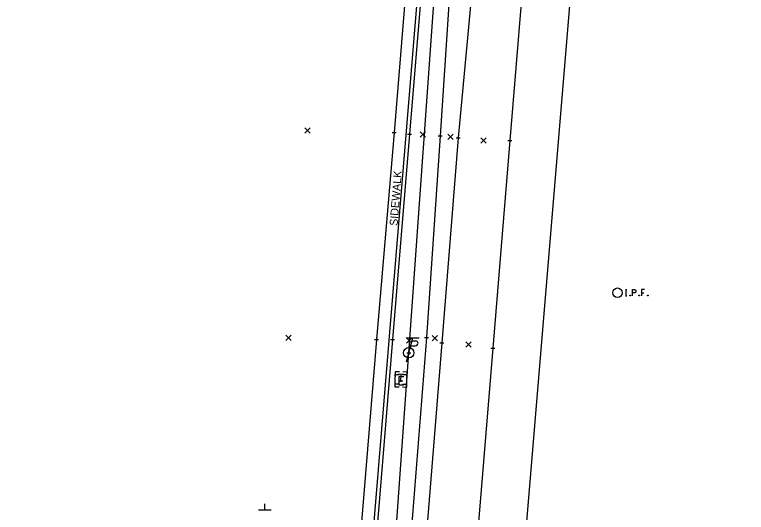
# Model space of a CAD drawing. Extents: x 1380440 to 1381945, y 468756 to 470369.
# Drawn here: x 1381482.8 to 1381665.6, y 469978.3 to 470102.7 of the extents above; entities that cross this region are included whole.
import ezdxf

# ---------------------------------------------------------------- set-up
doc = ezdxf.new("R2010")
doc.units = 0
for name, color, linetype in [('DR_P_Headwall', 7, 'Continuous'), ('GE_P_Driveway_CL', 7, 'Continuous'), ('PM_P_Cells', 7, 'Continuous'), ('PM_X_Cells', 7, 'Continuous'), ('PM_X_CL_Double_Solid', 7, 'Continuous'), ('PV_P_Curb', 7, 'Continuous'), ('PV_P_Drive', 7, 'Continuous'), ('PV_X_COP', 7, 'Continuous'), ('RW_P_Esmt_TMP', 7, 'Continuous'), ('SC_Scratch1', 7, 'Continuous'), ('SC_Shading1', 7, 'Continuous'), ('SH_Named_Boundary', 7, 'Continuous'), ('UT_X_Gas', 7, 'Continuous'), ('UT_X_Overhead_Combined', 7, 'Continuous'), ('UT_X_Water', 7, 'Continuous'), ('X-SUBDIVISION', 7, 'Continuous')]:
    doc.layers.add(name, color=color, linetype=linetype)

msp = doc.modelspace()

# ---------------------------------------------------------------- linework, layer by layer
at = {"layer": 'DR_P_Headwall'}
for points in [[(1381595.25, 470241), (1381595.01, 470239.38), (1381594.79, 470235.56), (1381591.94, 470203.13), (1381590.15, 470180.15), (1381585.84, 470126.11), (1381581.45, 470072.84), (1381577.22, 470021.47), (1381573.16, 469971.68), (1381569.7, 469929.43), (1381565.6, 469880.89), (1381564.41, 469867), (1381562.95, 469848.39), (1381561.9, 469840.88)], [(1381542.56, 470237.64), (1381568.34, 470236.69), (1381578.51, 470236.26), (1381584.49, 470236.02), (1381590.64, 470235.62), (1381587.95, 470203.42), (1381586.62, 470180.46), (1381581.93, 470126.46), (1381577.65, 470073.24), (1381573.2, 470021.54), (1381569.15, 469971.74), (1381565.64, 469929.65), (1381561.64, 469881.16), (1381560.46, 469867.32), (1381559.27, 469848.71), (1381558.35, 469840.14)]]:
    msp.add_lwpolyline(points, dxfattribs=at)
at = {"layer": 'GE_P_Driveway_CL'}
for p, q in [((1381555.34, 470073.03), (1381556.68, 470074.37)), ((1381555.34, 470074.37), (1381556.68, 470073.03)), ((1381584.13, 470072.03), (1381585.46, 470073.37)), ((1381584.13, 470073.37), (1381585.46, 470072.03)), ((1381591, 470071.5), (1381592.33, 470072.83)), ((1381591, 470072.83), (1381592.33, 470071.5)), ((1381599.22, 470070.57), (1381600.56, 470071.9)), ((1381599.22, 470071.9), (1381600.56, 470070.57)), ((1381550.55, 470021.28), (1381551.88, 470022.61)), ((1381550.55, 470022.61), (1381551.88, 470021.28)), ((1381587.09, 470021.17), (1381588.43, 470022.51)), ((1381587.09, 470022.51), (1381588.43, 470021.17)), ((1381580.68, 470020.59), (1381582.01, 470021.92)), ((1381580.68, 470021.92), (1381582.01, 470020.59)), ((1381595.47, 470019.55), (1381596.81, 470020.89)), ((1381595.47, 470020.89), (1381596.81, 470019.55))]:
    msp.add_line(p, q, dxfattribs=at)
at = {"layer": 'PM_P_Cells'}
for p, q in [((1381578.68, 470012.9), (1381579.98, 470012.87)), ((1381579.28, 470010.89), (1381579.33, 470012.89)), ((1381579.3, 470011.89), (1381579.3, 470011.89))]:
    msp.add_line(p, q, dxfattribs=at)
for points in [[(1381578.94, 470013.4), (1381577.84, 470013.42), (1381577.81, 470012.32)], [(1381580.81, 470012.26), (1381580.84, 470013.36), (1381579.74, 470013.38)], [(1381577.8, 470011.52), (1381577.77, 470010.42), (1381578.87, 470010.4)], [(1381579.67, 470010.38), (1381580.77, 470010.36), (1381580.79, 470011.46)]]:
    msp.add_lwpolyline(points, dxfattribs=at)
at = {"layer": 'PM_X_Cells'}
for p, q in [((1381578.8, 470011.17), (1381579.8, 470011.15)), ((1381579.3, 470011.16), (1381579.3, 470011.16))]:
    msp.add_line(p, q, dxfattribs=at)
for points in [[(1381578.93, 470012.67), (1381577.83, 470012.69), (1381577.81, 470011.59)], [(1381580.07, 470012.15), (1381578.82, 470012.17), (1381578.78, 470010.17), (1381580.03, 470010.15)], [(1381580.81, 470011.53), (1381580.83, 470012.63), (1381579.73, 470012.65)], [(1381577.79, 470010.79), (1381577.77, 470009.69), (1381578.87, 470009.67)], [(1381579.67, 470009.65), (1381580.77, 470009.63), (1381580.79, 470010.73)]]:
    msp.add_lwpolyline(points, dxfattribs=at)
at = {"layer": 'PM_X_CL_Double_Solid'}
msp.add_lwpolyline([(1381618.76, 470220.14), (1381616.92, 470200.19), (1381615.1, 470178.83), (1381610.95, 470124.78), (1381606.49, 470071.23), (1381602.26, 470019.36), (1381598.18, 469969.8), (1381595.01, 469928.06), (1381590.91, 469878.81), (1381589.36, 469859.11), (1381585.99, 469815.58), (1381581.29, 469760.78), (1381580.3, 469747.86), (1381578.72, 469729.45), (1381576.78, 469708.95), (1381575.29, 469689.79), (1381572.76, 469657.56), (1381569.36, 469615.7), (1381565.36, 469567.23), (1381561.16, 469537.52), (1381558.94, 469486.81), (1381555.39, 469442.03), (1381550.97, 469391.02)], dxfattribs=at)
at = {"layer": 'PV_P_Curb'}
msp.add_lwpolyline([(1381599.49, 470202.78), (1381597.12, 470179.51), (1381597.25, 470175.53), (1381597.2, 470175.03), (1381592.57, 470125.52), (1381589.1, 470072.43), (1381585.65, 470022.01), (1381581.71, 469971.4), (1381577.66, 469928.75), (1381573.1, 469880.44), (1381570.64, 469867.29)], dxfattribs=at)
at = {"layer": 'PV_P_Drive'}
for p, q in [((1381545.3, 469978.84), (1381545.3, 469980.44)), ((1381546.9, 469978.84), (1381543.7, 469978.84))]:
    msp.add_line(p, q, dxfattribs=at)
at = {"layer": 'PV_X_COP'}
for p, q in [((1381582.23, 470021.8), (1381580.62, 470015.8)), ((1381583.83, 470021.8), (1381580.63, 470021.8)), ((1381582.07, 470021.2), (1381582.92, 470021.2)), ((1381581.73, 470019.92), (1381582.92, 470019.92))]:
    msp.add_line(p, q, dxfattribs=at)
msp.add_circle((1381581.26, 470018.2), 1.3, dxfattribs=at)
msp.add_arc((1381582.93, 470020.56), 0.638, 268.8767, 91.1233, dxfattribs=at)
at = {"layer": 'RW_P_Esmt_TMP'}
msp.add_lwpolyline([(1381575.39, 470244.04), (1381576.99, 470244.17), (1381579.54, 470245.54), (1381580.63, 470247.96), (1381580.96, 470249.54), (1381591.47, 470243.59), (1381595.25, 470241), (1381599.72, 470235.67), (1381603.29, 470229.19), (1381604.88, 470222.31), (1381604.1, 470201.73), (1381602.36, 470179.43), (1381598.63, 470125.51), (1381593.59, 470071.89), (1381589.53, 470020.65), (1381585.49, 469971.09), (1381582.04, 469928.84), (1381578.38, 469880.28), (1381576.86, 469862.02), (1381576.83, 469860.71), (1381576.16, 469857.38), (1381571.59, 469847.12), (1381563.14, 469838.25)], dxfattribs=at)
at = {"layer": 'SC_Scratch1'}
for points in [[(1381635.4, 470033.97), (1381635.75, 470033.97)], [(1381635.57, 470032.37), (1381635.57, 470033.97)], [(1381637.14, 470032.37), (1381637.14, 470033.97), (1381637.67, 470033.97), (1381637.72, 470033.95), (1381637.8, 470033.93), (1381637.83, 470033.9), (1381637.87, 470033.88), (1381637.91, 470033.81), (1381637.94, 470033.75), (1381637.96, 470033.65), (1381637.96, 470033.5), (1381637.95, 470033.45), (1381637.93, 470033.37), (1381637.89, 470033.28), (1381637.84, 470033.25), (1381637.81, 470033.22), (1381637.76, 470033.2), (1381637.67, 470033.18), (1381637.14, 470033.18)], [(1381640.15, 470033.97), (1381639.39, 470033.97), (1381639.39, 470032.37)], [(1381635.4, 470032.37), (1381635.75, 470032.37)], [(1381636.53, 470032.58), (1381636.59, 470032.58), (1381636.62, 470032.55), (1381636.65, 470032.5), (1381636.65, 470032.44), (1381636.62, 470032.39), (1381636.59, 470032.37), (1381636.53, 470032.37), (1381636.5, 470032.39), (1381636.47, 470032.44), (1381636.47, 470032.5), (1381636.5, 470032.55), (1381636.53, 470032.58)], [(1381638.78, 470032.58), (1381638.84, 470032.58), (1381638.87, 470032.55), (1381638.9, 470032.5), (1381638.9, 470032.44), (1381638.87, 470032.39), (1381638.84, 470032.37), (1381638.78, 470032.37), (1381638.75, 470032.39), (1381638.71, 470032.44), (1381638.71, 470032.5), (1381638.75, 470032.55), (1381638.78, 470032.58)], [(1381639.39, 470033.18), (1381639.93, 470033.18)], [(1381640.93, 470032.58), (1381640.98, 470032.58), (1381641.02, 470032.55), (1381641.05, 470032.5), (1381641.05, 470032.44), (1381641.02, 470032.39), (1381640.98, 470032.37), (1381640.93, 470032.37), (1381640.9, 470032.39), (1381640.86, 470032.44), (1381640.86, 470032.5), (1381640.9, 470032.55), (1381640.93, 470032.58)]]:
    msp.add_lwpolyline(points, dxfattribs=at)
msp.add_circle((1381633.38, 470033.17), 1.2, dxfattribs=at)
at = {"layer": 'SC_Shading1'}
msp.add_lwpolyline([(1381627.41, 470324.23), (1381625.02, 470294.42), (1381622.34, 470259.95), (1381618.76, 470220.14), (1381616.92, 470200.19), (1381615.1, 470178.83), (1381610.95, 470124.78), (1381606.49, 470071.23), (1381602.26, 470019.36), (1381598.18, 469969.8), (1381595.01, 469928.06), (1381590.91, 469878.81), (1381589.36, 469859.11), (1381585.99, 469815.58)], dxfattribs=at)
at = {"layer": 'SH_Named_Boundary'}
for p, q in [((1381577.65, 470073.74), (1381577.65, 470072.74)), ((1381577.15, 470073.24), (1381578.15, 470073.24)), ((1381577.65, 470073.24), (1381577.65, 470073.24)), ((1381580.95, 470072.84), (1381581.95, 470072.84)), ((1381581.45, 470073.34), (1381581.45, 470072.34)), ((1381581.45, 470072.84), (1381581.45, 470072.84)), ((1381588.6, 470072.43), (1381589.6, 470072.43)), ((1381589.1, 470072.93), (1381589.1, 470071.93)), ((1381589.1, 470072.43), (1381589.1, 470072.43)), ((1381593.09, 470071.89), (1381594.09, 470071.89)), ((1381593.59, 470072.39), (1381593.59, 470071.39)), ((1381593.59, 470071.89), (1381593.59, 470071.89)), ((1381606.49, 470071.73), (1381606.49, 470070.73)), ((1381605.99, 470071.23), (1381606.99, 470071.23)), ((1381606.49, 470071.23), (1381606.49, 470071.23)), ((1381585.65, 470022.51), (1381585.65, 470021.51)), ((1381572.7, 470021.54), (1381573.7, 470021.54)), ((1381573.2, 470022.04), (1381573.2, 470021.04)), ((1381573.2, 470021.54), (1381573.2, 470021.54)), ((1381576.72, 470021.47), (1381577.72, 470021.47)), ((1381577.22, 470021.97), (1381577.22, 470020.97)), ((1381577.22, 470021.47), (1381577.22, 470021.47)), ((1381585.15, 470022.01), (1381586.15, 470022.01)), ((1381585.65, 470022.01), (1381585.65, 470022.01)), ((1381589.03, 470020.65), (1381590.03, 470020.65)), ((1381589.53, 470021.15), (1381589.53, 470020.15)), ((1381589.53, 470020.65), (1381589.53, 470020.65)), ((1381581.26, 470018.7), (1381581.26, 470017.7)), ((1381581.26, 470018.7), (1381581.26, 470017.7)), ((1381601.76, 470019.36), (1381602.76, 470019.36)), ((1381602.26, 470019.86), (1381602.26, 470018.86)), ((1381602.26, 470019.36), (1381602.26, 470019.36)), ((1381580.76, 470018.2), (1381581.76, 470018.2)), ((1381580.76, 470018.2), (1381581.76, 470018.2)), ((1381581.26, 470018.2), (1381581.26, 470018.2)), ((1381581.26, 470018.2), (1381581.26, 470018.2))]:
    msp.add_line(p, q, dxfattribs=at)
at = {"layer": 'UT_X_Gas'}
msp.add_lwpolyline([(1381485.9, 468926.41), (1381594.27, 470237.89), (1380558, 470279.29)], dxfattribs=at)
at = {"layer": 'UT_X_Overhead_Combined'}
msp.add_lwpolyline([(1381540.8, 469054.26), (1381515.28, 469203.1), (1381529.17, 469390.12), (1381543.86, 469565.78), (1381559.77, 469757.41), (1381571.97, 469887.64), (1381581.26, 470018.2), (1381595.79, 470220.83), (1381665.56, 470247.4)], dxfattribs=at)
at = {"layer": 'UT_X_Water'}
msp.add_line((1381545.41, 469194.71), (1381630.26, 470209.69), dxfattribs=at)

# ---------------------------------------------------------------- texts
at = {"layer": 'X-SUBDIVISION'}
msp.add_text('SIDEWALK', height=2, rotation=85.521, dxfattribs=at).set_placement((1381578.45, 470049.83))

doc.saveas('drawing.dxf')
